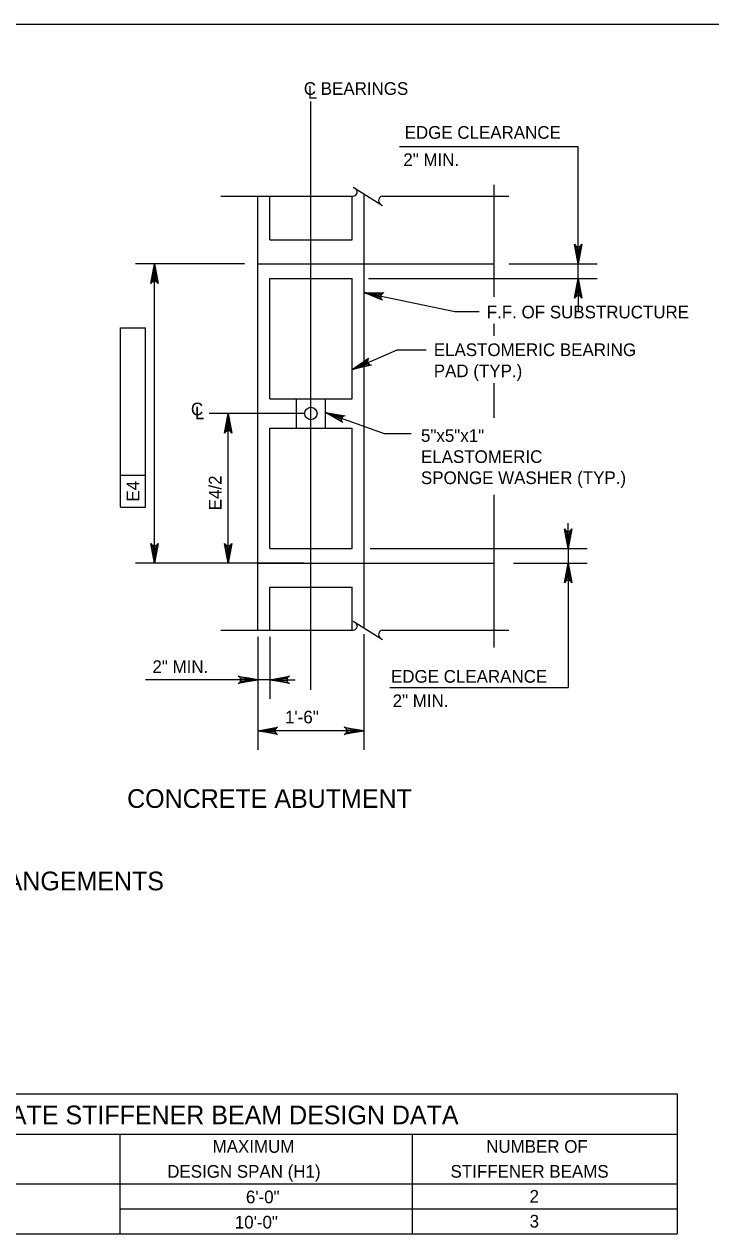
# Model space of a CAD drawing. Extents: x 638268 to 640277, y 295465 to 298435.
# Drawn here: x 639926.8 to 640089.4, y 297539.8 to 297826.5 of the extents above; entities that cross this region are included whole.
import ezdxf

# ---------------------------------------------------------------- set-up
doc = ezdxf.new("R2010")
doc.units = 0
for name, color, linetype in [('2', 7, 'Continuous'), ('3', 7, 'Continuous'), ('4', 7, 'Continuous'), ('8', 7, 'Continuous')]:
    doc.layers.add(name, color=color, linetype=linetype)

msp = doc.modelspace()

# ---------------------------------------------------------------- linework, layer by layer
at = {"layer": '2'}
msp.add_line((639316.46, 297826.46), (640102.46, 297826.46), dxfattribs=at)
at = {"layer": '3'}
for p, q in [((640004.71, 297787.87), (640011.64, 297783.51)), ((640038.02, 297788.37), (640038.02, 297761.88)), ((639973.35, 297785.69), (640004.63, 297785.69)), ((639982.12, 297682.85), (639982.12, 297785.69)), ((640007.22, 297786.29), (640007.22, 297683.45)), ((640011.63, 297785.69), (640041.52, 297785.69)), ((639984.93, 297775.38), (640004.41, 297775.38)), ((639978.92, 297769.64), (639953.09, 297769.64)), ((639957.59, 297698.77), (639957.59, 297769.64)), ((639982.12, 297769.64), (640038.02, 297769.64)), ((639984.93, 297766.19), (640004.41, 297766.19)), ((640038.02, 297755.46), (640038.02, 297752.64)), ((640038.02, 297741.36), (640038.02, 297733.14)), ((639984.93, 297737.65), (640004.41, 297737.65)), ((639984.93, 297730.76), (640004.41, 297730.76)), ((640038.02, 297714.9), (640038.02, 297678.78)), ((639984.93, 297702.22), (640004.41, 297702.22)), ((639979.62, 297698.77), (639953.09, 297698.77)), ((639982.12, 297698.77), (640038.02, 297698.77)), ((639984.93, 297693.03), (640004.41, 297693.03)), ((640004.71, 297685.03), (640011.64, 297680.68)), ((639973.35, 297682.85), (640004.63, 297682.85)), ((640011.63, 297682.85), (640041.52, 297682.85))]:
    msp.add_line(p, q, dxfattribs=at)
for points in [[(639957.09, 297766.64), (639958.09, 297766.64), (639957.59, 297769.64)], [(639957.09, 297701.77), (639958.09, 297701.77), (639957.59, 297698.77)]]:
    msp.add_lwpolyline(points, close=True, dxfattribs=at)
for centre, start, end in [((640004.63, 297786.71), 270, 60), ((640011.72, 297784.67), 95.3286, 237.8672), ((640004.63, 297683.88), 270, 60), ((640011.72, 297681.83), 95.3286, 237.8672)]:
    msp.add_arc(centre, 1.02, start, end, dxfattribs=at)
at = {"layer": '4'}
for p, q in [((639994.67, 297668.74), (639994.67, 297808.16)), ((640015.69, 297797.49), (640057.96, 297797.49)), ((640057.96, 297769.64), (640057.96, 297797.49)), ((640041.52, 297769.64), (640062.46, 297769.64)), ((640057.96, 297766.19), (640057.96, 297769.64)), ((640008.28, 297766.19), (640062.46, 297766.19)), ((640057.96, 297766.19), (640057.96, 297758.34)), ((640028.73, 297758.36), (640034.52, 297758.36)), ((639949.56, 297712.01), (639949.56, 297754.53)), ((639949.56, 297754.53), (639955.46, 297754.53)), ((639955.46, 297712.01), (639955.46, 297754.53)), ((640015.13, 297749.27), (640021.98, 297749.27)), ((639993.11, 297734.2), (639970.56, 297734.2)), ((639975.06, 297698.77), (639975.06, 297734.2)), ((640012.02, 297729.44), (640018.39, 297729.44)), ((639949.56, 297719.57), (639955.46, 297719.57)), ((639949.56, 297712.01), (639955.46, 297712.01)), ((640055.59, 297705.22), (640055.59, 297708.22)), ((640008.71, 297702.22), (640060.09, 297702.22)), ((640055.59, 297702.22), (640055.59, 297698.77)), ((639993.11, 297698.77), (639970.56, 297698.77)), ((640042.65, 297698.77), (640060.09, 297698.77)), ((640055.59, 297695.77), (640055.59, 297669.24)), ((640007.22, 297681.89), (640007.22, 297654.5)), ((639982.12, 297681.29), (639982.12, 297666.62)), ((639982.12, 297681.29), (639982.12, 297654.5)), ((639984.93, 297681.29), (639984.93, 297666.62)), ((639979.12, 297671.12), (639955.51, 297671.12)), ((639984.93, 297671.12), (639982.12, 297671.12)), ((639987.93, 297671.12), (639990.93, 297671.12)), ((640013.33, 297669.24), (640055.59, 297669.24)), ((640007.22, 297659), (639982.12, 297659))]:
    msp.add_line(p, q, dxfattribs=at)
for points in [[(640057.96, 297769.64), (640057.08, 297774.3), (640057.33, 297773.94), (640057.64, 297773.75), (640057.96, 297773.7), (640058.27, 297773.75), (640058.58, 297773.94), (640058.83, 297774.3), (640057.96, 297769.64), (640058.58, 297773.94), (640058.27, 297773.75), (640057.96, 297769.64), (640057.96, 297773.7), (640057.64, 297773.75), (640057.96, 297769.64), (640057.33, 297773.94)], [(639957.59, 297769.64), (639958.47, 297764.98), (639958.22, 297765.34), (639957.91, 297765.52), (639957.59, 297765.57), (639957.28, 297765.52), (639956.97, 297765.34), (639956.72, 297764.98), (639957.59, 297769.64), (639956.97, 297765.34), (639957.28, 297765.52), (639957.59, 297769.64), (639957.59, 297765.57), (639957.91, 297765.52), (639957.59, 297769.64), (639958.22, 297765.34)], [(640057.96, 297766.19), (640058.83, 297761.53), (640058.58, 297761.89), (640058.27, 297762.08), (640057.96, 297762.13), (640057.64, 297762.08), (640057.33, 297761.89), (640057.08, 297761.53), (640057.96, 297766.19), (640057.33, 297761.89), (640057.64, 297762.08), (640057.96, 297766.19), (640057.96, 297762.13), (640058.27, 297762.08), (640057.96, 297766.19), (640058.58, 297761.89)], [(640007.22, 297762.89), (640028.73, 297758.36)], [(640007.22, 297762.89), (640011.96, 297762.78), (640011.56, 297762.61), (640011.31, 297762.35), (640011.19, 297762.05), (640011.18, 297761.74), (640011.3, 297761.39), (640011.6, 297761.07), (640007.22, 297762.89), (640011.3, 297761.39), (640011.18, 297761.74), (640007.22, 297762.89), (640011.19, 297762.05), (640011.31, 297762.35), (640007.22, 297762.89), (640011.56, 297762.61)], [(640004.41, 297744.64), (640015.13, 297749.26)], [(640004.41, 297744.64), (640008.35, 297747.29), (640008.12, 297746.92), (640008.07, 297746.56), (640008.14, 297746.25), (640008.32, 297745.99), (640008.61, 297745.77), (640009.04, 297745.69), (640004.41, 297744.64), (640008.61, 297745.77), (640008.32, 297745.99), (640004.41, 297744.64), (640008.14, 297746.25), (640008.07, 297746.56), (640004.41, 297744.64), (640008.12, 297746.92)], [(639975.06, 297734.2), (639975.94, 297729.54), (639975.69, 297729.9), (639975.38, 297730.09), (639975.06, 297730.14), (639974.75, 297730.09), (639974.44, 297729.9), (639974.19, 297729.54), (639975.06, 297734.2), (639974.44, 297729.9), (639974.75, 297730.09), (639975.06, 297734.2), (639975.06, 297730.14), (639975.38, 297730.09), (639975.06, 297734.2), (639975.69, 297729.9)], [(639998.11, 297734.44), (640012.02, 297729.44)], [(639998.11, 297734.44), (640002.79, 297733.69), (640002.37, 297733.57), (640002.09, 297733.34), (640001.94, 297733.07), (640001.88, 297732.75), (640001.95, 297732.4), (640002.2, 297732.04), (639998.11, 297734.44), (640001.95, 297732.4), (640001.88, 297732.75), (639998.11, 297734.44), (640001.94, 297733.07), (640002.09, 297733.34), (639998.11, 297734.44), (640002.37, 297733.57)], [(640055.59, 297702.22), (640054.72, 297706.88), (640054.97, 297706.52), (640055.28, 297706.33), (640055.59, 297706.28), (640055.91, 297706.33), (640056.22, 297706.52), (640056.47, 297706.88), (640055.59, 297702.22), (640056.22, 297706.52), (640055.91, 297706.33), (640055.59, 297702.22), (640055.59, 297706.28), (640055.28, 297706.33), (640055.59, 297702.22), (640054.97, 297706.52)], [(639957.59, 297698.77), (639956.72, 297703.43), (639956.97, 297703.07), (639957.28, 297702.89), (639957.59, 297702.83), (639957.91, 297702.89), (639958.22, 297703.07), (639958.47, 297703.43), (639957.59, 297698.77), (639958.22, 297703.07), (639957.91, 297702.89), (639957.59, 297698.77), (639957.59, 297702.83), (639957.28, 297702.89), (639957.59, 297698.77), (639956.97, 297703.07)], [(639975.06, 297698.77), (639974.19, 297703.43), (639974.44, 297703.07), (639974.75, 297702.89), (639975.06, 297702.83), (639975.38, 297702.89), (639975.69, 297703.07), (639975.94, 297703.43), (639975.06, 297698.77), (639975.69, 297703.07), (639975.38, 297702.89), (639975.06, 297698.77), (639975.06, 297702.83), (639974.75, 297702.89), (639975.06, 297698.77), (639974.44, 297703.07)], [(640055.59, 297698.77), (640056.47, 297694.11), (640056.22, 297694.47), (640055.91, 297694.65), (640055.59, 297694.71), (640055.28, 297694.65), (640054.97, 297694.47), (640054.72, 297694.11), (640055.59, 297698.77), (640054.97, 297694.47), (640055.28, 297694.65), (640055.59, 297698.77), (640055.59, 297694.71), (640055.91, 297694.65), (640055.59, 297698.77), (640056.22, 297694.47)], [(639982.12, 297671.12), (639977.46, 297670.24), (639977.82, 297670.49), (639978, 297670.8), (639978.06, 297671.12), (639978, 297671.43), (639977.82, 297671.74), (639977.46, 297671.99), (639982.12, 297671.12), (639977.82, 297671.74), (639978, 297671.43), (639982.12, 297671.12), (639978.06, 297671.12), (639978, 297670.8), (639982.12, 297671.12), (639977.82, 297670.49)], [(639984.93, 297671.12), (639989.59, 297671.99), (639989.23, 297671.74), (639989.04, 297671.43), (639988.99, 297671.12), (639989.04, 297670.8), (639989.23, 297670.49), (639989.59, 297670.24), (639984.93, 297671.12), (639989.23, 297670.49), (639989.04, 297670.8), (639984.93, 297671.12), (639988.99, 297671.12), (639989.04, 297671.43), (639984.93, 297671.12), (639989.23, 297671.74)], [(639982.12, 297659), (639986.78, 297659.87), (639986.42, 297659.62), (639986.24, 297659.31), (639986.18, 297659), (639986.24, 297658.68), (639986.42, 297658.37), (639986.78, 297658.12), (639982.12, 297659), (639986.42, 297658.37), (639986.24, 297658.68), (639982.12, 297659), (639986.18, 297659), (639986.24, 297659.31), (639982.12, 297659), (639986.42, 297659.62)], [(640007.22, 297659), (640002.56, 297658.12), (640002.92, 297658.37), (640003.1, 297658.68), (640003.16, 297659), (640003.1, 297659.31), (640002.92, 297659.62), (640002.56, 297659.87), (640007.22, 297659), (640002.92, 297659.62), (640003.1, 297659.31), (640007.22, 297659), (640003.16, 297659), (640003.1, 297658.68), (640007.22, 297659), (640002.92, 297658.37)]]:
    msp.add_lwpolyline(points, dxfattribs=at)
for points in [[(640057.46, 297772.64), (640058.46, 297772.64), (640057.96, 297769.64)], [(640057.46, 297763.19), (640058.46, 297763.19), (640057.96, 297766.19)], [(640007.22, 297762.89), (640010.1, 297762.03), (640010.21, 297762.52)], [(639974.56, 297731.2), (639975.56, 297731.2), (639975.06, 297734.2)], [(640055.09, 297705.22), (640056.09, 297705.22), (640055.59, 297702.22)], [(640055.09, 297695.77), (640056.09, 297695.77), (640055.59, 297698.77)], [(639979.12, 297671.62), (639979.12, 297670.62), (639982.12, 297671.12)], [(639987.93, 297671.62), (639987.93, 297670.62), (639984.93, 297671.12)], [(639985.12, 297659.5), (639985.12, 297658.5), (639982.12, 297659)], [(640004.22, 297659.5), (640004.22, 297658.5), (640007.22, 297659)]]:
    msp.add_lwpolyline(points, close=True, dxfattribs=at)
at = {"layer": '8'}
for p, q in [((639984.93, 297775.38), (639984.93, 297785.69)), ((640004.41, 297775.38), (640004.41, 297785.69)), ((639984.93, 297737.65), (639984.93, 297766.19)), ((640004.41, 297737.65), (640004.41, 297766.19)), ((639991.22, 297730.76), (639991.22, 297737.65)), ((639998.11, 297730.76), (639998.11, 297737.65)), ((639984.93, 297702.22), (639984.93, 297730.76)), ((640004.41, 297702.22), (640004.41, 297730.76)), ((639984.93, 297682.85), (639984.93, 297693.03)), ((640004.41, 297682.85), (640004.41, 297693.03)), ((639859.24, 297572.99), (640081.44, 297572.99)), ((640081.44, 297572.99), (640081.44, 297539.82)), ((639859.24, 297563.45), (640081.44, 297563.45)), ((639949.44, 297563.45), (639949.44, 297539.82)), ((640018.67, 297563.45), (640018.67, 297539.82)), ((639859.24, 297551.64), (640081.44, 297551.64)), ((639949.44, 297545.73), (640081.44, 297545.73)), ((639859.24, 297539.82), (640081.44, 297539.82))]:
    msp.add_line(p, q, dxfattribs=at)
msp.add_circle((639994.67, 297734.2), 1.48, dxfattribs=at)

# ---------------------------------------------------------------- texts
at = {"layer": '3'}
for s, p in [('CONCRETE ABUTMENT', (639951.13, 297640.75)), ('ELASTOMERIC BEARING PAD ARRANGEMENTS', (639823.62, 297621.22))]:
    msp.add_text(s, height=4.4292, dxfattribs=at).set_placement(p)
at = {"layer": '4'}
for s, height, p in [('C BEARINGS', 3, (639992.99, 297809.71)), ('L', 3, (639993.94, 297808.8)), ('EDGE CLEARANCE', 3, (640016.87, 297799.31)), ('2" MIN.', 3, (640016.56, 297792.85)), ('F.F. OF SUBSTRUCTURE', 3, (640036.33, 297756.75)), ('ELASTOMERIC BEARING', 3, (640023.78, 297747.81)), ('PAD (TYP.)', 3, (640023.78, 297742.81)), ('C', 3, (639966.25, 297733.77)), ('L', 3, (639967.2, 297732.86)), ('5"x5"x1"', 3, (640020.74, 297727.48)), ('ELASTOMERIC', 3, (640020.74, 297722.48)), ('SPONGE WASHER (TYP.)', 3, (640020.74, 297717.48)), ('2" MIN.', 3, (639957.13, 297672.72)), ('EDGE CLEARANCE', 3, (640013.64, 297670.41)), ('2" MIN.', 3, (640014.03, 297664.63)), ('1\'-6"', 3, (639988.54, 297660.78)), ('TABLE 1 - INTERMEDIATE STIFFENER BEAM DESIGN DATA', 4.4292, (639861.81, 297565.78)), ('MAXIMUM', 3, (639971.38, 297559.02)), ('NUMBER OF ', 3, (640036.19, 297559.02)), ('DESIGN SPAN (H1)', 3, (639960.63, 297553.11)), ('STIFFENER BEAMS', 3, (640027.75, 297553.12)), ('6\'-0"', 3, (639979.27, 297547.06)), ('2', 3, (640046.47, 297547.21)), ('10\'-0"', 3, (639976.64, 297541.08)), ('3', 3, (640046.48, 297541.31))]:
    msp.add_text(s, height=height, dxfattribs=at).set_placement(p)
for s, rotation, p in [('E4/2', 90, (639973.5, 297711.27)), ('E4', 89.9359, (639954.01, 297713.33))]:
    msp.add_text(s, height=3, rotation=rotation, dxfattribs=at).set_placement(p)

doc.saveas('drawing.dxf')
